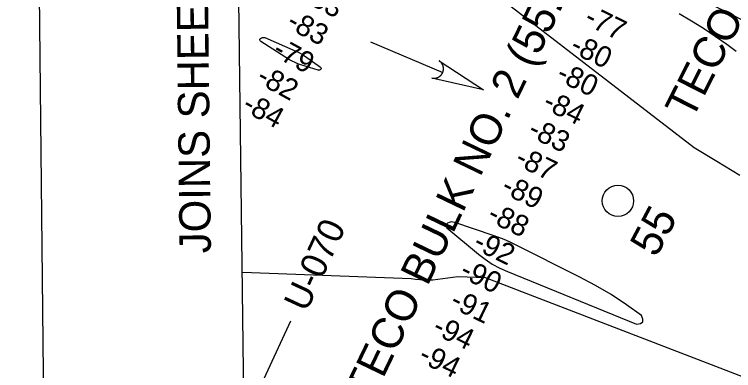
# Model space of a CAD drawing. Extents: x 3734862 to 3772949, y 391520 to 417239.
# Drawn here: x 3738202 to 3740497, y 406999 to 408137 of the extents above; entities that cross this region are included whole.
import ezdxf

# ---------------------------------------------------------------- set-up
doc = ezdxf.new("R2010")
doc.units = 0
for name, color, linetype in [('V-ANNO-SYMB', 7, 'Continuous'), ('V-ANNO-TEXT', 7, 'Continuous'), ('V-CHAN-NAID', 7, 'Continuous'), ('V-GRID-FRAM', 7, 'Continuous'), ('V-RIVR-IDEN', 7, 'Continuous'), ('V-RIVR-MILE', 7, 'Continuous'), ('V-RIVR-RANG', 7, 'Continuous'), ('V-RIVR-RANG-IDEN', 7, 'Continuous'), ('V-STRM-FLOW', 7, 'Continuous'), ('V-TOPO-MINR', 7, 'Continuous')]:
    doc.layers.add(name, color=color, linetype=linetype)

msp = doc.modelspace()

# ---------------------------------------------------------------- linework, layer by layer
at = {"layer": 'V-ANNO-SYMB'}
msp.add_lwpolyline([(3738444.4, 392757.5), (3771525.7, 393106.9), (3771283.7, 416022.2), (3738202.3, 415672.8), (3738444.4, 392757.5)], dxfattribs=at)
at = {"layer": 'V-GRID-FRAM'}
msp.add_lwpolyline([(3738832.3, 415033.8), (3770599.2, 415447.4), (3770843.8, 397266.6), (3739061.1, 396852.8), (3738832.3, 415033.8)], dxfattribs=at)
at = {"layer": 'V-RIVR-MILE'}
msp.add_circle((3740127.8, 407541.2), 50, dxfattribs=at)
at = {"layer": 'V-RIVR-RANG'}
msp.add_line((3738935.5, 406835.4), (3739084.1, 407158.7), dxfattribs=at)
at = {"layer": 'V-STRM-FLOW'}
msp.add_line((3739338.3, 408049), (3739568.8, 407951.2), dxfattribs=at)
msp.add_lwpolyline([(3739557.5, 407988.6), (3739699.1, 407895.8), (3739534.1, 407933.3), (3739537, 407932.8), (3739540, 407932.6), (3739541.2, 407932.6), (3739542.2, 407932.6), (3739543.5, 407932.7), (3739544.7, 407932.9), (3739545.7, 407933), (3739547.1, 407933.3), (3739548.7, 407933.7), (3739549.5, 407933.9), (3739550.6, 407934.2), (3739551.9, 407934.7), (3739553, 407935.2), (3739554.1, 407935.7), (3739554.8, 407936.1), (3739555.6, 407936.5), (3739556.6, 407937), (3739557.4, 407937.6), (3739558.3, 407938.1), (3739558.9, 407938.6), (3739559.9, 407939.4), (3739560.8, 407940.1), (3739561.5, 407940.8), (3739562.3, 407941.5), (3739562.9, 407942.2), (3739563.5, 407942.8), (3739563.9, 407943.3), (3739564.6, 407944.1), (3739565.2, 407944.9), (3739565.8, 407945.7), (3739566.3, 407946.5), (3739566.8, 407947.3), (3739567.3, 407948.2), (3739567.7, 407948.9), (3739568.2, 407950), (3739568.8, 407951.2), (3739569, 407951.6), (3739569.2, 407952.1), (3739569.4, 407952.8), (3739569.7, 407953.5), (3739569.9, 407954.2), (3739570.1, 407954.8), (3739570.3, 407955.6), (3739570.4, 407956.1), (3739570.6, 407956.9), (3739570.7, 407957.6), (3739570.8, 407958.2), (3739571, 407959.5), (3739571.1, 407960.2), (3739571.1, 407960.7), (3739571.2, 407961.5), (3739571.2, 407962.2), (3739571.2, 407963), (3739571.2, 407963.9), (3739571.2, 407964.7), (3739571.1, 407965.4), (3739571.1, 407966), (3739571, 407966.7), (3739570.9, 407967.4), (3739570.8, 407968.2), (3739570.6, 407969), (3739570.5, 407969.8), (3739570.2, 407970.8), (3739570, 407971.5), (3739569.8, 407972.3), (3739569.6, 407973), (3739569.3, 407973.6), (3739569.1, 407974.3), (3739568.7, 407975.3), (3739568.7, 407975.3), (3739568.4, 407975.9), (3739568.2, 407976.3), (3739567.9, 407976.9), (3739567.5, 407977.7), (3739567.2, 407978.3), (3739566.9, 407978.8), (3739566.5, 407979.5), (3739566, 407980.1), (3739565.7, 407980.5), (3739565.3, 407981.1), (3739564.7, 407981.9), (3739564.4, 407982.3), (3739564.1, 407982.7), (3739563.8, 407983), (3739563.5, 407983.4), (3739563, 407983.9), (3739562.6, 407984.3), (3739562.1, 407984.8), (3739561.7, 407985.3), (3739561.1, 407985.8), (3739560.7, 407986.1), (3739560.1, 407986.7), (3739559.4, 407987.2), (3739558.8, 407987.7), (3739558.4, 407988), (3739558, 407988.2), (3739557.7, 407988.4)], close=True, dxfattribs=at)
at = {"layer": 'V-TOPO-MINR'}
for points in [[(3740516.2, 407622), (3740443.7, 407666.5), (3740370.8, 407710.5), (3739537, 408354.2), (3739494.3, 408383.3), (3739451.7, 408412.6), (3739416.4, 408437.2), (3739391.8, 408454.8), (3739367.6, 408472.9), (3739343.9, 408491.7), (3739320.6, 408511), (3739252.4, 408569.1), (3739229.3, 408588.9), (3739206.4, 408608.8), (3739183.6, 408628.9), (3739161, 408649.2), (3739138.2, 408669.2), (3739115.1, 408689), (3739091.6, 408708.2), (3739067.8, 408727.1), (3739015.1, 408768), (3738964.6, 408806.8), (3738913.9, 408845.4), (3738910.1, 408848.2)], [(3741004.5, 407876.8), (3740258, 408253.9)], [(3740505.2, 408017.7), (3740475.1, 408040.1), (3740438.2, 408066.4), (3740400.7, 408091.7), (3740362.2, 408115.4), (3740323, 408138.2)], [(3739180.8, 407964.8), (3739180.6, 407963.1), (3739179.7, 407961.4), (3739177.9, 407960), (3739176, 407959), (3739173.9, 407958.8), (3739171.6, 407959.1), (3739116.4, 407975.6), (3739107, 407978.9), (3739097.7, 407982.6), (3739088.8, 407987.1), (3739080.1, 407992.1), (3738988.1, 408049.9), (3738986.1, 408052.3), (3738985.1, 408054.8), (3738985.7, 408057.4), (3738987.2, 408060.1), (3738990.6, 408062.1), (3738994, 408063.3), (3738997.7, 408063.3), (3739001.5, 408062.4), (3739099.8, 408019.7), (3739107.1, 408016.2), (3739114.3, 408012.5), (3739121.2, 408008.3), (3739127.9, 408003.9), (3739179, 407968), (3739180.2, 407966.4), (3739180.8, 407964.8)], [(3740106.3, 407241.8), (3740055.8, 407271.4), (3740004.1, 407299.2), (3739798.9, 407402), (3739782.1, 407410), (3739765, 407417.5), (3739747.7, 407424.3), (3739730.2, 407430.7), (3739607.1, 407472.5), (3739601.1, 407473.7), (3739595.2, 407473.9), (3739589.4, 407472.6), (3739583.6, 407470.3), (3739580.6, 407466.9), (3739579.1, 407463.3), (3739579.9, 407459.6), (3739582.3, 407455.6), (3739682.8, 407371.2), (3739704.5, 407354.7), (3739727, 407339.6), (3739750.9, 407326.7), (3739775.6, 407315.2), (3740187.1, 407147.8), (3740199.3, 407149.8), (3740206.7, 407154.6), (3740207.1, 407163.4), (3740202.6, 407175), (3740155.1, 407209.3), (3740106.3, 407241.8)], [(3740569.5, 406962.6), (3739704.9, 407295.4), (3739616.6, 407299.2), (3739537.5, 407288), (3739523.6, 407288), (3739509.7, 407288.5), (3739495.8, 407289.4), (3739482, 407290.7), (3739468.2, 407292.2), (3738929.5, 407312.4)]]:
    msp.add_lwpolyline(points, dxfattribs=at)

# ---------------------------------------------------------------- texts
at = {"layer": 'V-ANNO-TEXT'}
msp.add_text('JOINS SHEET 59', height=100, rotation=90.6517, dxfattribs=at).set_placement((3738829.4, 407374.4))
at = {"layer": 'V-CHAN-NAID'}
for s, rotation, p in [('TECO BULK', 63.2032, (3740364.1, 407796.4)), ('TECO BULK NO. 2 (55.4)', 64.2775, (3739342.8, 406898.2))]:
    msp.add_text(s, height=100, rotation=rotation, dxfattribs=at).set_placement(p)
at = {"layer": 'V-RIVR-IDEN'}
msp.add_text('55', height=100, rotation=61.9503, dxfattribs=at).set_placement((3740249.7, 407357.3))
at = {"layer": 'V-RIVR-RANG'}
for s, rotation, p in [('-83', 331.3453, (3739114.7, 408184.5)), ('-77', 333.9499, (3740016.3, 408107.7)), ('-83', 331.3453, (3739066.5, 408096.8)), ('-79', 331.3453, (3739021.8, 408007.3)), ('-80', 333.9499, (3739971.2, 408018.4)), ('-82', 331.3453, (3738970.6, 407921.3)), ('-80', 333.9499, (3739927.1, 407928.7)), ('-84', 331.3453, (3738925, 407832.3)), ('-84', 333.9499, (3739883.9, 407838.5)), ('-83', 333.9499, (3739836.7, 407750.3)), ('-87', 333.9499, (3739795.1, 407659.3)), ('-89', 333.9499, (3739751.5, 407569.3)), ('-88', 333.9499, (3739706.6, 407479.9)), ('-92', 333.9499, (3739661.6, 407390.6)), ('-90', 333.9499, (3739619.1, 407300.1)), ('-91', 333.9499, (3739588.2, 407203.9)), ('-94', 333.9499, (3739531.8, 407120.2)), ('-94', 333.9499, (3739487.6, 407030.4))]:
    msp.add_text(s, height=67, rotation=rotation, dxfattribs=at).set_placement(p)
at = {"layer": 'V-RIVR-RANG-IDEN'}
msp.add_text('U-070', height=83, rotation=65.1633, dxfattribs=at).set_placement((3739134.2, 407183.3))

doc.saveas('drawing.dxf')
